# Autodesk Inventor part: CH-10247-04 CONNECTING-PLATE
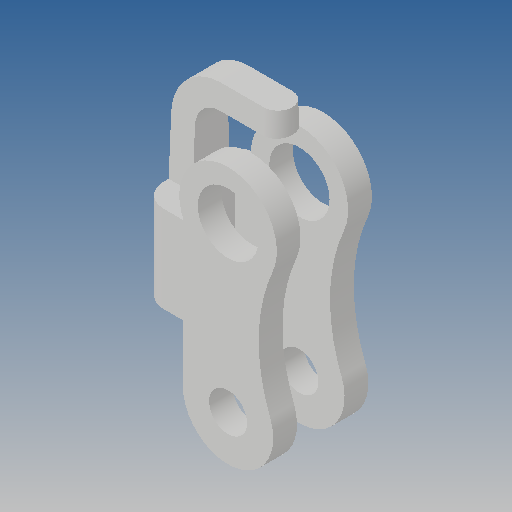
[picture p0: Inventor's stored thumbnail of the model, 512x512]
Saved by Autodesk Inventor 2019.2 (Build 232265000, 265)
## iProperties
Created: 2012-09
Part Number: CH-10247-04 CONNECTING-PLATE
Material: Ogólny
Document SubType Name: Modeling
Designer: CADENGINEERING4
Density: 1 g/cm^3
Appearance: Domyślna
Author: CADENGINEERING4
Revision Number: ÈÎºÎ
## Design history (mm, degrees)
feature "Ô²½Ç2"
node "Bryła1"
